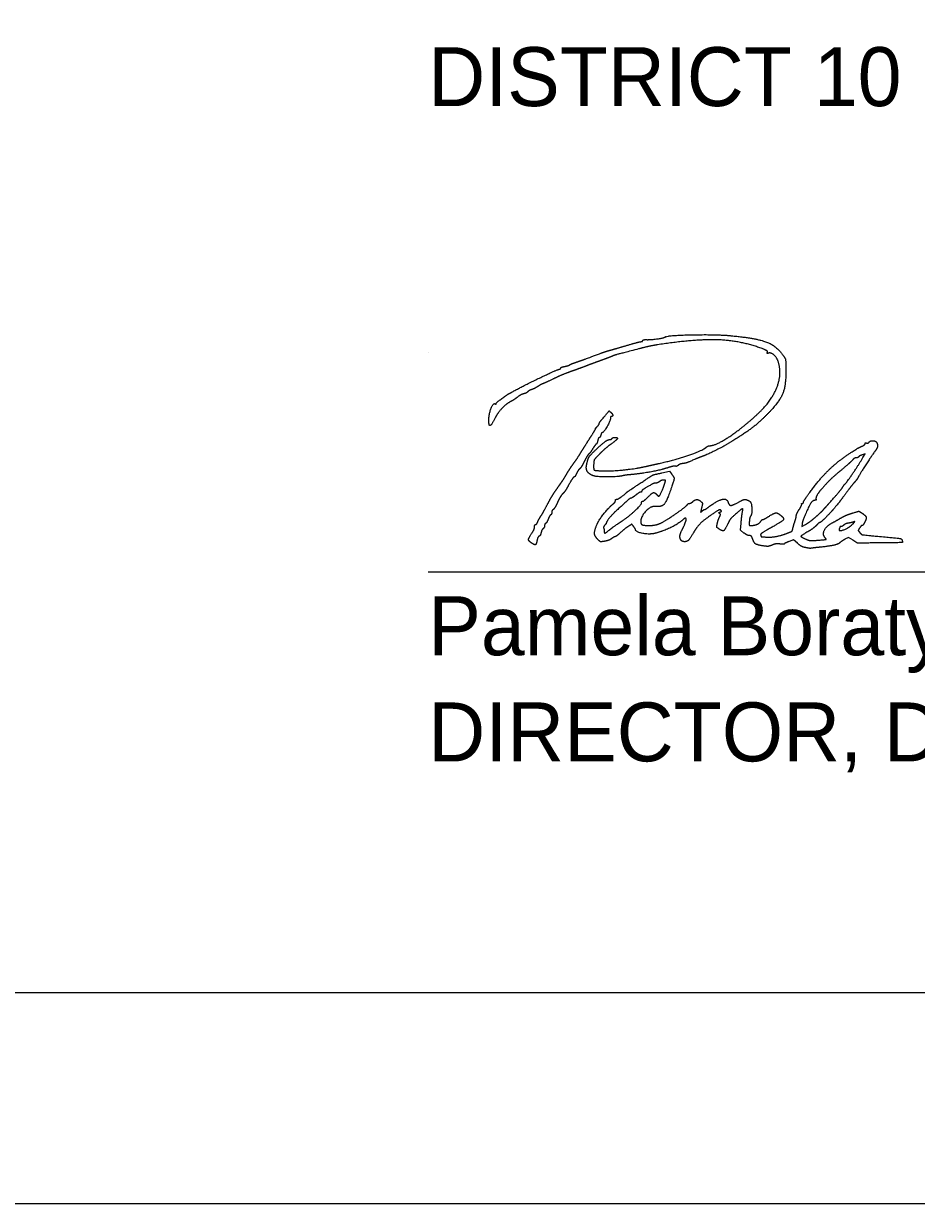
# Model space of a CAD drawing. Extents: x -84548 to 2262448, y -162180 to 525962.
# Drawn here: x 129567 to 140758, y 0 to 14797 of the extents above; entities that cross this region are included whole.
import ezdxf

# ---------------------------------------------------------------- set-up
doc = ezdxf.new("R2010")
doc.units = 0
for name, color, linetype in [('Default', 7, 'Continuous'), ('GM_X_Adjacent_County', 7, 'Continuous'), ('GM_X_County', 7, 'Continuous'), ('GM_X_Section', 7, 'Continuous'), ('GM_X_Township', 7, 'Continuous')]:
    doc.layers.add(name, color=color, linetype=linetype)

msp = doc.modelspace()

# ---------------------------------------------------------------- linework, layer by layer
at = {"layer": 'Default'}
for points in [[(140088, 9353), (140116, 9400), (140078, 9387)], [(137568, 9162), (137663, 9184), (137687, 9151)], [(138597, 8408), (138553, 8442), (138561, 8532)], [(139326, 8524), (139320, 8490), (139366, 8514)], [(139267, 8280), (139219, 8324), (139163, 8302)], [(139964, 8317), (139907, 8353), (139863, 8329)]]:
    msp.add_lwpolyline(points, dxfattribs=at)
for points in [[(137133, 10762), (137218, 10787), (137296, 10808), (137307, 10808)], [(137307, 10808), (137318, 10808), (137327, 10814), (137327, 10821)], [(137327, 10821), (137327, 10828), (137348, 10834), (137375, 10833)], [(137375, 10833), (137425, 10831), (137589, 10854), (137607, 10866)], [(138825, 10720), (138558, 10820), (137988, 10841), (137511, 10768)], [(137607, 10866), (137643, 10888), (138261, 10900), (138442, 10882)], [(138442, 10882), (138755, 10851), (139006, 10755), (139089, 10633)], [(136503, 10553), (136581, 10580), (136615, 10593), (136801, 10662)], [(136801, 10662), (136843, 10677), (136900, 10696), (136928, 10703)], [(136928, 10703), (136956, 10711), (137048, 10737), (137133, 10762)], [(137276, 10717), (137007, 10647), (136984, 10641), (136928, 10618)], [(137511, 10768), (137462, 10761), (137356, 10738), (137276, 10717)], [(138890, 10674), (138895, 10687), (138877, 10700), (138825, 10720)], [(138903, 10663), (138889, 10658), (138885, 10661), (138890, 10674)], [(139026, 10558), (139009, 10609), (138933, 10675), (138903, 10663)], [(136348, 10497), (136374, 10502), (136401, 10510), (136408, 10515)], [(136408, 10515), (136415, 10521), (136458, 10538), (136503, 10553)], [(136630, 10507), (136585, 10490), (136499, 10459), (136440, 10438)], [(136807, 10573), (136755, 10554), (136675, 10525), (136630, 10507)], [(136928, 10618), (136914, 10612), (136860, 10592), (136807, 10573)], [(138786, 9918), (138949, 10073), (139075, 10409), (139026, 10558)], [(139089, 10633), (139116, 10595), (139120, 10572), (139122, 10477)], [(135680, 10172), (135839, 10258), (136228, 10446), (136272, 10459)], [(136440, 10438), (136381, 10417), (136273, 10372), (136201, 10338)], [(136272, 10459), (136288, 10464), (136301, 10472), (136301, 10478)], [(136301, 10478), (136301, 10484), (136322, 10492), (136348, 10497)], [(139122, 10477), (139126, 10262), (139041, 10052), (138886, 9895)], [(136012, 10246), (135986, 10229), (135951, 10212), (135934, 10206)], [(136065, 10276), (136062, 10276), (136038, 10262), (136012, 10246)], [(136201, 10338), (136129, 10304), (136068, 10276), (136065, 10276)], [(135490, 10032), (135490, 10043), (135624, 10142), (135680, 10172)], [(135756, 10111), (135731, 10092), (135694, 10067), (135672, 10056)], [(135834, 10153), (135815, 10149), (135780, 10130), (135756, 10111)], [(135885, 10179), (135876, 10169), (135853, 10158), (135834, 10153)], [(135934, 10206), (135917, 10201), (135895, 10188), (135885, 10179)], [(135399, 9832), (135399, 9901), (135456, 10042), (135477, 10028)], [(135477, 10028), (135484, 10024), (135490, 10026), (135490, 10032)], [(135672, 10056), (135617, 10028), (135512, 9918), (135479, 9854)], [(136811, 9826), (136909, 9943), (136905, 9940), (136926, 9922)], [(136926, 9922), (136949, 9903), (136954, 9870), (136934, 9870)], [(138170, 9503), (138244, 9503), (138604, 9745), (138786, 9918)], [(135406, 9759), (135402, 9764), (135399, 9796), (135399, 9832)], [(135479, 9854), (135444, 9786), (135416, 9749), (135406, 9759)], [(136757, 9743), (136771, 9757), (136782, 9774), (136782, 9780)], [(136782, 9780), (136782, 9787), (136795, 9807), (136811, 9826)], [(136922, 9843), (136922, 9814), (136837, 9667), (136821, 9667)], [(136934, 9870), (136927, 9870), (136922, 9858), (136922, 9843)], [(138886, 9895), (138788, 9795), (138617, 9663), (138456, 9564)], [(136573, 9450), (136608, 9507), (136660, 9590), (136689, 9635)], [(136689, 9635), (136719, 9681), (136740, 9718), (136737, 9718)], [(136737, 9718), (136734, 9718), (136743, 9729), (136757, 9743)], [(136802, 9636), (136798, 9618), (136789, 9604), (136783, 9604)], [(136821, 9667), (136815, 9667), (136807, 9653), (136802, 9636)], [(136743, 9521), (136736, 9517), (136716, 9489), (136698, 9460)], [(136738, 9451), (136821, 9528), (136888, 9579), (136909, 9579)], [(136763, 9566), (136759, 9545), (136749, 9525), (136743, 9521)], [(136783, 9604), (136777, 9604), (136768, 9587), (136763, 9566)], [(136931, 9524), (136887, 9492), (136821, 9434), (136784, 9397)], [(136909, 9579), (136922, 9579), (136936, 9584), (136941, 9591)], [(137010, 9593), (137010, 9587), (136975, 9556), (136931, 9524)], [(136941, 9591), (136950, 9607), (137010, 9608), (137010, 9593)], [(137536, 9281), (137731, 9325), (138081, 9445), (138126, 9485)], [(138456, 9564), (138354, 9501), (138136, 9390), (138062, 9364)], [(138126, 9485), (138137, 9495), (138157, 9503), (138170, 9503)], [(139921, 9406), (140021, 9470), (140030, 9476), (140074, 9495)], [(140074, 9495), (140096, 9506), (140115, 9521), (140115, 9529)], [(140115, 9529), (140115, 9537), (140123, 9540), (140133, 9536)], [(140133, 9536), (140143, 9533), (140158, 9538), (140166, 9548)], [(140166, 9548), (140175, 9558), (140194, 9566), (140209, 9566)], [(140209, 9566), (140259, 9566), (140279, 9481), (140240, 9434)], [(136458, 9277), (136487, 9316), (136538, 9394), (136573, 9450)], [(136649, 9395), (136641, 9388), (136616, 9347), (136595, 9305)], [(136625, 9268), (136640, 9337), (136672, 9390), (136738, 9451)], [(136698, 9460), (136680, 9431), (136658, 9402), (136649, 9395)], [(136784, 9397), (136728, 9339), (136716, 9319), (136713, 9276)], [(137979, 9331), (137889, 9292), (137864, 9283), (137829, 9279)], [(138062, 9364), (138038, 9355), (138000, 9340), (137979, 9331)], [(139421, 8917), (139539, 9080), (139776, 9312), (139921, 9406)], [(139957, 9322), (139943, 9306), (139877, 9248), (139811, 9192)], [(139862, 9021), (139877, 9031), (140026, 9251), (140088, 9353)], [(140004, 9351), (139992, 9351), (139971, 9338), (139957, 9322)], [(140032, 9362), (140028, 9356), (140015, 9351), (140004, 9351)], [(140240, 9434), (140218, 9407), (140045, 9141), (140028, 9108)], [(140078, 9387), (140056, 9380), (140036, 9368), (140032, 9362)], [(136370, 9141), (136390, 9176), (136430, 9237), (136458, 9277)], [(136535, 9211), (136524, 9202), (136507, 9175), (136497, 9152)], [(136595, 9305), (136574, 9263), (136547, 9221), (136535, 9211)], [(136706, 9127), (136651, 9147), (136613, 9213), (136625, 9268)], [(136713, 9276), (136709, 9205), (136730, 9190), (136839, 9187)], [(136839, 9187), (136941, 9184), (137246, 9216), (137359, 9242)], [(137641, 9226), (137554, 9198), (137316, 9153), (137190, 9141)], [(137359, 9242), (137401, 9251), (137480, 9269), (137536, 9281)], [(137736, 9246), (137727, 9249), (137684, 9240), (137641, 9226)], [(137772, 9257), (137761, 9248), (137744, 9242), (137736, 9246)], [(137829, 9279), (137808, 9276), (137782, 9267), (137772, 9257)], [(139811, 9192), (139707, 9105), (139645, 9045), (139557, 8945)], [(136230, 8931), (136251, 8962), (136283, 9007), (136301, 9032)], [(136301, 9032), (136319, 9058), (136350, 9107), (136370, 9141)], [(136467, 9110), (136460, 9110), (136431, 9068), (136403, 9017)], [(136497, 9152), (136487, 9129), (136474, 9110), (136467, 9110)], [(137082, 9127), (137010, 9111), (136748, 9111), (136706, 9127)], [(137190, 9141), (137146, 9137), (137097, 9131), (137082, 9127)], [(137283, 9023), (137450, 9134), (137457, 9138), (137568, 9162)], [(137491, 9034), (137479, 9034), (137456, 9026), (137439, 9017)], [(137537, 9052), (137523, 9042), (137503, 9034), (137491, 9034)], [(137529, 8869), (137538, 8869), (137590, 8981), (137606, 9037)], [(137589, 9071), (137574, 9071), (137550, 9063), (137537, 9052)], [(137606, 9037), (137615, 9067), (137613, 9072), (137589, 9071)], [(137687, 9151), (137722, 9105), (137722, 9079), (137681, 8960)], [(139982, 9044), (139967, 9027), (139920, 8967), (139878, 8911)], [(140028, 9108), (140019, 9090), (139998, 9061), (139982, 9044)], [(136130, 8761), (136163, 8824), (136208, 8900), (136230, 8931)], [(136325, 8900), (136310, 8886), (136281, 8838), (136260, 8793)], [(136403, 9017), (136375, 8966), (136340, 8913), (136325, 8900)], [(137076, 8875), (137148, 8934), (137138, 8927), (137283, 9023)], [(137238, 8882), (137212, 8861), (137185, 8844), (137179, 8844)], [(137300, 8920), (137293, 8920), (137265, 8903), (137238, 8882)], [(137314, 8931), (137314, 8925), (137308, 8920), (137300, 8920)], [(137439, 9017), (137363, 8975), (137314, 8942), (137314, 8931)], [(137390, 8856), (137444, 8910), (137478, 8919), (137504, 8888)], [(137681, 8960), (137627, 8802), (137563, 8733), (137479, 8740)], [(137504, 8888), (137513, 8878), (137524, 8869), (137529, 8869)], [(139342, 8794), (139342, 8801), (139378, 8857), (139421, 8917)], [(139557, 8945), (139526, 8910), (139493, 8842), (139501, 8830)], [(139676, 8794), (139757, 8885), (139829, 8971), (139841, 8994)], [(139878, 8911), (139836, 8855), (139796, 8801), (139788, 8791)], [(139841, 8994), (139848, 9005), (139857, 9018), (139862, 9021)], [(136048, 8616), (136060, 8633), (136097, 8699), (136130, 8761)], [(136260, 8793), (136239, 8748), (136214, 8706), (136204, 8700)], [(136755, 8517), (136779, 8572), (136902, 8728), (136956, 8772)], [(136956, 8772), (136972, 8784), (136985, 8803), (136985, 8813)], [(136985, 8813), (136985, 8823), (136993, 8831), (137003, 8831)], [(137179, 8844), (137169, 8844), (137125, 8805), (136991, 8683)], [(137003, 8831), (137012, 8831), (137045, 8851), (137076, 8875)], [(137071, 8560), (137153, 8615), (137314, 8766), (137314, 8789)], [(137479, 8740), (137424, 8745), (137302, 8611), (137302, 8546)], [(137314, 8789), (137314, 8798), (137320, 8806), (137327, 8806)], [(137327, 8806), (137334, 8806), (137362, 8828), (137390, 8856)], [(137663, 8596), (137761, 8661), (137879, 8750), (137888, 8764)], [(137888, 8764), (137894, 8773), (137906, 8780), (137916, 8780)], [(137916, 8780), (137926, 8780), (137943, 8790), (137954, 8801)], [(137954, 8801), (137980, 8827), (138033, 8827), (138059, 8801)], [(138059, 8801), (138076, 8785), (138077, 8772), (138066, 8723)], [(138105, 8704), (138110, 8704), (138133, 8718), (138155, 8735)], [(138155, 8735), (138262, 8815), (138382, 8844), (138397, 8794)], [(138397, 8794), (138410, 8754), (138453, 8754), (138523, 8792)], [(138523, 8792), (138586, 8827), (138624, 8831), (138668, 8807)], [(138668, 8807), (138691, 8794), (138700, 8646), (138679, 8619)], [(139290, 8705), (139311, 8738), (139324, 8769), (139320, 8773)], [(139320, 8773), (139316, 8777), (139319, 8780), (139327, 8780)], [(139327, 8780), (139335, 8780), (139342, 8786), (139342, 8794)], [(139489, 8818), (139456, 8818), (139405, 8738), (139342, 8584)], [(139501, 8830), (139505, 8824), (139499, 8818), (139489, 8818)], [(139594, 8702), (139610, 8721), (139647, 8762), (139676, 8794)], [(139788, 8791), (139718, 8705), (139694, 8678), (139631, 8613)], [(136012, 8549), (136020, 8568), (136036, 8598), (136048, 8616)], [(136173, 8634), (136166, 8630), (136151, 8604), (136140, 8576)], [(136187, 8666), (136187, 8653), (136181, 8639), (136173, 8634)], [(136204, 8700), (136195, 8695), (136187, 8680), (136187, 8666)], [(136991, 8683), (136943, 8638), (136871, 8548), (136871, 8532)], [(137407, 8502), (137476, 8502), (137577, 8539), (137663, 8596)], [(137872, 8579), (137872, 8595), (137851, 8593), (137832, 8574)], [(138199, 8643), (138095, 8572), (138004, 8482), (137961, 8407)], [(138066, 8723), (138053, 8669), (138054, 8667), (138074, 8685)], [(138074, 8685), (138086, 8696), (138100, 8704), (138105, 8704)], [(138306, 8693), (138297, 8703), (138265, 8688), (138199, 8643)], [(138261, 8518), (138265, 8541), (138277, 8578), (138287, 8601)], [(138291, 8653), (138279, 8660), (138281, 8665), (138297, 8671)], [(138287, 8601), (138303, 8634), (138303, 8645), (138291, 8653)], [(138297, 8671), (138313, 8677), (138316, 8684), (138306, 8693)], [(138523, 8672), (138439, 8598), (138419, 8574), (138390, 8515)], [(138576, 8663), (138586, 8713), (138572, 8715), (138523, 8672)], [(138561, 8532), (138565, 8581), (138572, 8640), (138576, 8663)], [(138679, 8619), (138672, 8610), (138666, 8580), (138664, 8552)], [(138835, 8578), (138842, 8578), (138874, 8595), (138907, 8616)], [(139056, 8631), (139107, 8591), (139071, 8549), (138904, 8456)], [(138907, 8616), (138975, 8659), (139015, 8663), (139056, 8631)], [(139235, 8552), (139245, 8584), (139253, 8617), (139253, 8627)], [(139253, 8627), (139253, 8637), (139270, 8672), (139290, 8705)], [(139342, 8584), (139336, 8570), (139329, 8543), (139326, 8524)], [(139366, 8514), (139391, 8527), (139446, 8567), (139488, 8603)], [(139488, 8603), (139529, 8639), (139577, 8683), (139594, 8702)], [(139631, 8613), (139592, 8573), (139554, 8540), (139549, 8540)], [(139701, 8534), (139716, 8542), (139763, 8568), (139804, 8592)], [(139804, 8592), (139846, 8616), (139916, 8646), (139959, 8659)], [(139959, 8659), (140033, 8681), (140040, 8681), (140071, 8661)], [(140071, 8661), (140121, 8628), (140134, 8589), (140109, 8541)], [(135940, 8409), (135957, 8434), (135971, 8468), (135971, 8484)], [(135971, 8484), (135971, 8501), (135977, 8514), (135984, 8514)], [(135984, 8514), (135991, 8514), (136004, 8530), (136012, 8549)], [(136080, 8464), (136070, 8456), (136058, 8432), (136053, 8411)], [(136098, 8503), (136098, 8490), (136090, 8473), (136080, 8464)], [(136109, 8527), (136103, 8527), (136098, 8516), (136098, 8503)], [(136140, 8576), (136129, 8549), (136115, 8527), (136109, 8527)], [(136764, 8328), (136724, 8369), (136721, 8436), (136755, 8517)], [(136851, 8505), (136840, 8494), (136835, 8477), (136838, 8467)], [(136838, 8467), (136842, 8457), (136845, 8441), (136845, 8431)], [(136845, 8431), (136845, 8405), (136864, 8409), (136905, 8442)], [(136871, 8532), (136871, 8528), (136862, 8516), (136851, 8505)], [(136905, 8442), (136944, 8474), (136972, 8494), (137071, 8560)], [(137154, 8495), (137111, 8467), (137098, 8456), (137038, 8403)], [(137214, 8488), (137190, 8519), (137190, 8519), (137154, 8495)], [(137238, 8449), (137238, 8454), (137227, 8471), (137214, 8488)], [(137479, 8403), (137411, 8387), (137239, 8420), (137238, 8449)], [(137302, 8546), (137302, 8519), (137343, 8502), (137407, 8502)], [(137832, 8574), (137781, 8526), (137577, 8427), (137479, 8403)], [(137852, 8299), (137807, 8299), (137786, 8382), (137816, 8438)], [(137816, 8438), (137838, 8479), (137872, 8565), (137872, 8579)], [(138285, 8458), (138259, 8475), (138254, 8485), (138261, 8518)], [(138390, 8515), (138355, 8442), (138330, 8428), (138285, 8458)], [(138664, 8552), (138661, 8512), (138665, 8502), (138681, 8502)], [(138681, 8502), (138725, 8502), (138788, 8527), (138806, 8552)], [(138904, 8456), (138834, 8416), (138801, 8391), (138806, 8379)], [(138806, 8552), (138816, 8566), (138829, 8578), (138835, 8578)], [(139142, 8406), (139189, 8424), (139204, 8437), (139209, 8462)], [(139209, 8462), (139213, 8480), (139224, 8521), (139235, 8552)], [(139504, 8503), (139484, 8483), (139442, 8450), (139409, 8431)], [(139549, 8540), (139543, 8540), (139523, 8523), (139504, 8503)], [(139611, 8352), (139579, 8392), (139631, 8496), (139701, 8534)], [(139790, 8459), (139777, 8424), (139912, 8471), (139956, 8517)], [(139798, 8484), (139798, 8481), (139795, 8469), (139790, 8459)], [(139813, 8489), (139805, 8489), (139798, 8486), (139798, 8484)], [(139849, 8508), (139837, 8497), (139821, 8489), (139813, 8489)], [(139907, 8532), (139886, 8529), (139860, 8518), (139849, 8508)], [(139969, 8546), (139955, 8541), (139927, 8534), (139907, 8532)], [(139956, 8517), (139985, 8546), (139988, 8553), (139969, 8546)], [(140047, 8471), (140028, 8443), (140029, 8438), (140049, 8413)], [(140078, 8502), (140072, 8502), (140058, 8488), (140047, 8471)], [(140109, 8541), (140098, 8519), (140084, 8502), (140078, 8502)], [(135932, 8284), (135894, 8310), (135897, 8345), (135940, 8409)], [(136004, 8318), (135994, 8267), (135972, 8256), (135932, 8284)], [(136028, 8367), (136019, 8363), (136008, 8341), (136004, 8318)], [(136053, 8411), (136049, 8390), (136037, 8370), (136028, 8367)], [(136850, 8304), (136804, 8297), (136792, 8300), (136764, 8328)], [(136937, 8337), (136918, 8323), (136879, 8309), (136850, 8304)], [(136982, 8362), (136976, 8362), (136956, 8351), (136937, 8337)], [(137038, 8403), (137013, 8381), (136988, 8362), (136982, 8362)], [(137961, 8407), (137917, 8332), (137884, 8299), (137852, 8299)], [(138666, 8375), (138652, 8375), (138621, 8390), (138597, 8408)], [(138705, 8334), (138696, 8361), (138682, 8375), (138666, 8375)], [(138839, 8246), (138760, 8259), (138724, 8283), (138705, 8334)], [(138806, 8379), (138813, 8361), (138816, 8360), (138879, 8357)], [(138879, 8357), (138935, 8353), (139073, 8379), (139142, 8406)], [(139163, 8302), (139133, 8290), (139106, 8277), (139104, 8272)], [(139409, 8431), (139314, 8376), (139308, 8359), (139377, 8329)], [(139377, 8329), (139413, 8314), (139447, 8311), (139518, 8317)], [(139518, 8317), (139621, 8325), (139631, 8328), (139611, 8352)], [(139801, 8288), (139782, 8268), (139668, 8242), (139545, 8229)], [(139863, 8329), (139839, 8316), (139811, 8297), (139801, 8288)], [(140210, 8283), (140021, 8281), (140019, 8281), (139964, 8317)], [(140049, 8413), (140068, 8389), (140094, 8384), (140273, 8367)], [(140581, 8310), (140585, 8288), (140575, 8287), (140210, 8283)], [(140273, 8367), (140532, 8343), (140576, 8335), (140581, 8310)], [(138951, 8257), (138914, 8242), (138885, 8239), (138839, 8246)], [(139050, 8270), (139020, 8274), (138981, 8269), (138951, 8257)], [(139104, 8272), (139102, 8267), (139078, 8266), (139050, 8270)], [(139345, 8230), (139329, 8233), (139294, 8256), (139267, 8280)], [(139399, 8219), (139385, 8221), (139361, 8227), (139345, 8230)], [(139443, 8217), (139433, 8215), (139413, 8216), (139399, 8219)], [(139545, 8229), (139499, 8225), (139454, 8219), (139443, 8217)]]:
    msp.add_open_spline(points, degree=2, dxfattribs=at)
at = {"layer": 'GM_X_Adjacent_County'}
msp.add_lwpolyline([(7920, 113520), (176880, 113520), (176880, 2640), (7920, 2640)], close=True, dxfattribs=at)
at = {"layer": 'GM_X_County'}
for p, q in [((134640, 10677), (134640, 10677)), ((134640, 7920), (153120, 7920))]:
    msp.add_line(p, q, dxfattribs=at)
at = {"layer": 'GM_X_Township'}
msp.add_lwpolyline([(0, 0), (179520, 0), (179520, 116160), (0, 116160)], close=True, dxfattribs=at)

# ---------------------------------------------------------------- texts
at = {"layer": 'GM_X_Section'}
for s, p in [('DISTRICT 10 DEPUTY DIRECTOR', (134640, 13762)), ('Pamela Boratyn', (134640, 6875)), ('DIRECTOR, DEPARTMENT OF TRANSPORTATION', (134640, 5544))]:
    msp.add_text(s, height=739.2, dxfattribs=at).set_placement(p)

doc.saveas('drawing.dxf')
